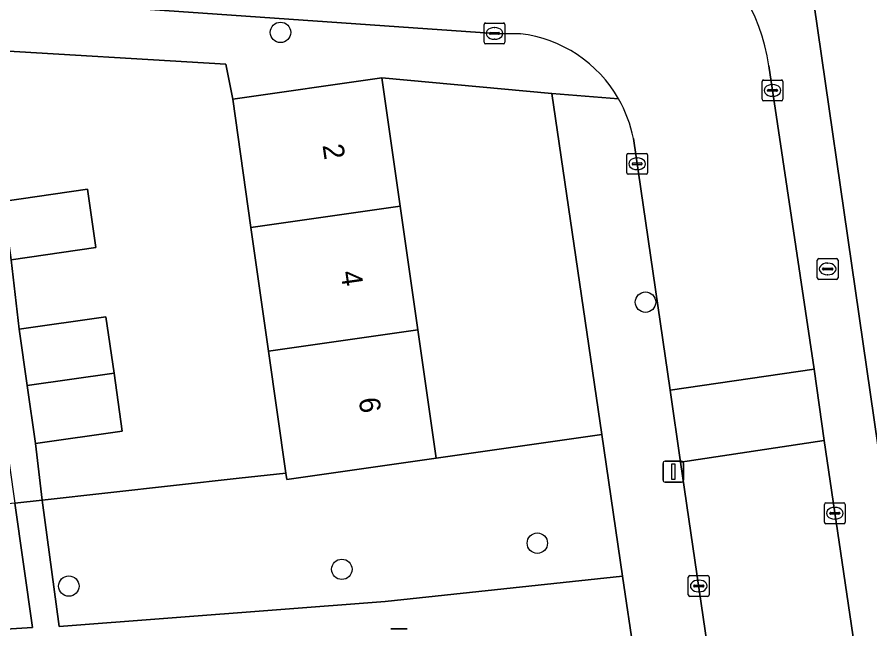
# Model space of a CAD drawing. Extents: x 159053 to 160042, y 380449 to 381423.
# Drawn here: x 159405.88 to 159446.78, y 381090.97 to 381120.32 of the extents above; entities that cross this region are included whole.
import ezdxf

# ---------------------------------------------------------------- set-up
doc = ezdxf.new("R2010")
doc.units = 0
for name, color, linetype in [('IMGEO_Boom', 7, 'Continuous'), ('IMGEO_Brandkraan', 7, 'Continuous'), ('IMGEO_Erf', 7, 'Continuous'), ('IMGEO_Groenvoorziening', 7, 'Continuous'), ('IMGEO_Kolk', 7, 'Continuous'), ('IMGEO_Lichtmast', 7, 'Continuous'), ('IMGEO_Muur', 7, 'Continuous'), ('IMGEO_Pand', 7, 'Continuous'), ('IMGEO_Pand_nummerreeks', 7, 'Continuous'), ('IMGEO_Rijbaan_lokaal_open', 7, 'Continuous'), ('IMGEO_Voetpad_open', 7, 'Continuous')]:
    doc.layers.add(name, color=color, linetype=linetype)

msp = doc.modelspace()

# ---------------------------------------------------------------- linework, layer by layer
at = {"layer": 'IMGEO_Boom'}
for centre in [(159418.511, 381119.583), (159436.016, 381106.642), (159430.829, 381095.081), (159421.453, 381093.827), (159408.362, 381093.023)]:
    msp.add_circle(centre, 0.489, dxfattribs=at)
at = {"layer": 'IMGEO_Brandkraan'}
for p, q in [((159444.251, 381107.808), (159444.251, 381108.66)), ((159444.326, 381108.734), (159445.178, 381108.734)), ((159444.739, 381108.514), (159444.764, 381108.514)), ((159445.252, 381108.66), (159445.252, 381107.808)), ((159444.51, 381108.228), (159444.51, 381108.24)), ((159444.948, 381108.191), (159444.55, 381108.191)), ((159444.553, 381108.277), (159444.951, 381108.277)), ((159444.994, 381108.24), (159444.994, 381108.228)), ((159445.178, 381107.734), (159444.326, 381107.734)), ((159444.762, 381107.954), (159444.737, 381107.954))]:
    msp.add_line(p, q, dxfattribs=at)
for points in [[(159444.251, 381107.808), (159444.251, 381108.66)], [(159444.326, 381108.734), (159445.178, 381108.734)], [(159445.252, 381108.66), (159445.252, 381107.808)], [(159445.178, 381107.734), (159444.326, 381107.734)]]:
    msp.add_lwpolyline(points, dxfattribs=at)
for centre, radius, start, end in [((159444.328, 381108.658), 0.0765, 91.552, 178.448), ((159444.328, 381108.658), 0.0765, 91.552, 178.448), ((159445.176, 381108.658), 0.0765, 1.552, 88.448), ((159445.176, 381108.658), 0.0765, 1.552, 88.448), ((159444.55, 381108.237), 0.0403, 85.8775, 175.7526), ((159444.547, 381108.227), 0.0366, 178.938, 274.7102), ((159444.951, 381108.234), 0.043, 264.8664, 352.4533), ((159444.955, 381108.239), 0.0386, 1.7309, 96.639), ((159444.328, 381107.81), 0.0765, 181.552, 268.448), ((159444.328, 381107.81), 0.0765, 181.552, 268.448), ((159445.176, 381107.81), 0.0765, 271.552, 358.448), ((159445.176, 381107.81), 0.0765, 271.552, 358.448)]:
    msp.add_arc(centre, radius, start, end, dxfattribs=at)
for centre, major_axis, ratio, start_param, end_param in [((159444.738, 381108.234), (-0.387, 0.002), 0.722429, 4.712389, 7.853982), ((159444.763, 381108.234), (-0.39, 0.002), 0.717154, 1.570796, 4.712389)]:
    msp.add_ellipse(centre, major_axis=major_axis, ratio=ratio, start_param=start_param, end_param=end_param, dxfattribs=at)
at = {"layer": 'IMGEO_Erf'}
for points in [[(159449.883, 381122.105), (159449.008, 381128.041), (159448.132, 381133.977), (159447.219, 381140.164), (159441.426, 381139.219), (159442.648, 381130.967), (159447.531, 381097.239), (159453.424, 381098.108), (159452.511, 381104.298), (159451.635, 381110.234), (159450.759, 381116.17)], [(159417.097, 381110.227), (159416.221, 381116.379), (159415.898, 381118.062), (159404.13, 381118.764), (159405.19, 381111.473), (159409.248, 381112.063), (159409.655, 381109.263), (159405.597, 381108.673), (159405.984, 381105.345), (159410.138, 381105.937), (159410.531, 381103.232), (159410.92, 381100.447), (159406.766, 381099.855), (159407.074, 381097.138), (159416.536, 381098.195), (159418.775, 381098.445), (159417.943, 381104.288)], [(159423.379, 381117.398), (159424.255, 381111.248), (159425.101, 381105.308), (159425.977, 381099.157), (159433.919, 381100.289), (159431.519, 381116.656)]]:
    msp.add_lwpolyline(points, close=True, dxfattribs=at)
at = {"layer": 'IMGEO_Groenvoorziening'}
for points in [[(159433.919, 381100.289), (159425.977, 381099.157), (159418.819, 381098.137), (159418.775, 381098.445), (159416.536, 381098.195), (159407.074, 381097.138), (159407.89, 381091.079), (159423.532, 381092.279), (159434.916, 381093.497)], [(159406.616, 381091.043), (159405.771, 381097), (159396.648, 381096.092), (159394.383, 381095.866), (159394.426, 381095.563), (159387.097, 381094.519), (159385.147, 381094.242), (159385.967, 381088.539), (159394.783, 381089.998), (159401.768, 381090.741)]]:
    msp.add_lwpolyline(points, close=True, dxfattribs=at)
at = {"layer": 'IMGEO_Kolk'}
for p, q in [((159428.276, 381119.106), (159428.276, 381119.958)), ((159428.351, 381120.032), (159429.203, 381120.032)), ((159429.277, 381119.958), (159429.277, 381119.106)), ((159428.535, 381119.526), (159428.535, 381119.538)), ((159428.973, 381119.489), (159428.575, 381119.489)), ((159428.578, 381119.575), (159428.976, 381119.575)), ((159428.764, 381119.812), (159428.789, 381119.812)), ((159429.019, 381119.538), (159429.019, 381119.526)), ((159429.203, 381119.032), (159428.351, 381119.032)), ((159428.787, 381119.252), (159428.762, 381119.252)), ((159441.607, 381116.372), (159441.607, 381117.224)), ((159441.682, 381117.298), (159442.534, 381117.298)), ((159442.095, 381117.078), (159442.12, 381117.078)), ((159442.608, 381117.224), (159442.608, 381116.372)), ((159441.866, 381116.792), (159441.866, 381116.804)), ((159442.304, 381116.755), (159441.906, 381116.755)), ((159441.909, 381116.841), (159442.307, 381116.841)), ((159442.35, 381116.804), (159442.35, 381116.792)), ((159442.534, 381116.298), (159441.682, 381116.298)), ((159442.118, 381116.518), (159442.093, 381116.518)), ((159435.115, 381112.852), (159435.115, 381113.704)), ((159435.19, 381113.778), (159436.042, 381113.778)), ((159436.116, 381113.704), (159436.116, 381112.852)), ((159435.417, 381113.321), (159435.815, 381113.321)), ((159435.603, 381113.558), (159435.628, 381113.558)), ((159435.374, 381113.272), (159435.374, 381113.284)), ((159435.812, 381113.235), (159435.414, 381113.235)), ((159435.626, 381112.998), (159435.601, 381112.998)), ((159435.858, 381113.284), (159435.858, 381113.272)), ((159436.042, 381112.778), (159435.19, 381112.778)), ((159444.596, 381096.091), (159444.596, 381096.943)), ((159444.671, 381097.017), (159445.523, 381097.017)), ((159445.597, 381096.943), (159445.597, 381096.091)), ((159444.898, 381096.56), (159445.296, 381096.56)), ((159445.084, 381096.797), (159445.109, 381096.797)), ((159444.855, 381096.511), (159444.855, 381096.523)), ((159445.293, 381096.474), (159444.895, 381096.474)), ((159445.107, 381096.237), (159445.082, 381096.237)), ((159445.339, 381096.523), (159445.339, 381096.511)), ((159445.523, 381096.017), (159444.671, 381096.017)), ((159438.069, 381092.601), (159438.069, 381093.453)), ((159438.144, 381093.527), (159438.996, 381093.527)), ((159438.557, 381093.307), (159438.582, 381093.307)), ((159439.07, 381093.453), (159439.07, 381092.601)), ((159438.328, 381093.021), (159438.328, 381093.033)), ((159438.766, 381092.984), (159438.368, 381092.984)), ((159438.371, 381093.07), (159438.769, 381093.07)), ((159438.812, 381093.033), (159438.812, 381093.021)), ((159438.996, 381092.527), (159438.144, 381092.527)), ((159438.58, 381092.747), (159438.555, 381092.747))]:
    msp.add_line(p, q, dxfattribs=at)
for points in [[(159428.276, 381119.106), (159428.276, 381119.958)], [(159428.351, 381120.032), (159429.203, 381120.032)], [(159429.277, 381119.958), (159429.277, 381119.106)], [(159429.203, 381119.032), (159428.351, 381119.032)], [(159441.607, 381116.372), (159441.607, 381117.224)], [(159441.682, 381117.298), (159442.534, 381117.298)], [(159442.608, 381117.224), (159442.608, 381116.372)], [(159442.534, 381116.298), (159441.682, 381116.298)], [(159435.115, 381112.852), (159435.115, 381113.704)], [(159435.19, 381113.778), (159436.042, 381113.778)], [(159436.116, 381113.704), (159436.116, 381112.852)], [(159436.042, 381112.778), (159435.19, 381112.778)], [(159444.596, 381096.091), (159444.596, 381096.943)], [(159444.671, 381097.017), (159445.523, 381097.017)], [(159445.597, 381096.943), (159445.597, 381096.091)], [(159445.523, 381096.017), (159444.671, 381096.017)], [(159438.069, 381092.601), (159438.069, 381093.453)], [(159438.144, 381093.527), (159438.996, 381093.527)], [(159439.07, 381093.453), (159439.07, 381092.601)], [(159438.996, 381092.527), (159438.144, 381092.527)]]:
    msp.add_lwpolyline(points, dxfattribs=at)
for centre, radius, start, end in [((159428.353, 381119.956), 0.0765, 91.552, 178.448), ((159428.353, 381119.956), 0.0765, 91.552, 178.448), ((159429.201, 381119.956), 0.0765, 1.552, 88.448), ((159429.201, 381119.956), 0.0765, 1.552, 88.448), ((159428.575, 381119.535), 0.0403, 85.8775, 175.7526), ((159428.572, 381119.525), 0.0366, 178.938, 274.7102), ((159428.976, 381119.532), 0.043, 264.8664, 352.4533), ((159428.98, 381119.537), 0.0386, 1.7309, 96.639), ((159428.353, 381119.108), 0.0765, 181.552, 268.448), ((159428.353, 381119.108), 0.0765, 181.552, 268.448), ((159429.201, 381119.108), 0.0765, 271.552, 358.448), ((159429.201, 381119.108), 0.0765, 271.552, 358.448), ((159441.684, 381117.222), 0.0765, 91.552, 178.448), ((159441.684, 381117.222), 0.0765, 91.552, 178.448), ((159442.532, 381117.222), 0.0765, 1.552, 88.448), ((159442.532, 381117.222), 0.0765, 1.552, 88.448), ((159441.906, 381116.801), 0.0403, 85.8775, 175.7526), ((159441.903, 381116.791), 0.0366, 178.938, 274.7102), ((159442.307, 381116.798), 0.043, 264.8664, 352.4533), ((159442.311, 381116.803), 0.0386, 1.7309, 96.639), ((159441.684, 381116.374), 0.0765, 181.552, 268.448), ((159441.684, 381116.374), 0.0765, 181.552, 268.448), ((159442.532, 381116.374), 0.0765, 271.552, 358.448), ((159442.532, 381116.374), 0.0765, 271.552, 358.448), ((159435.192, 381113.702), 0.0765, 91.552, 178.448), ((159435.192, 381113.702), 0.0765, 91.552, 178.448), ((159436.04, 381113.702), 0.0765, 1.552, 88.448), ((159436.04, 381113.702), 0.0765, 1.552, 88.448), ((159435.414, 381113.281), 0.0403, 85.8775, 175.7526), ((159435.819, 381113.283), 0.0386, 1.7309, 96.639), ((159435.411, 381113.271), 0.0366, 178.938, 274.7102), ((159435.815, 381113.278), 0.043, 264.8664, 352.4533), ((159435.192, 381112.854), 0.0765, 181.552, 268.448), ((159435.192, 381112.854), 0.0765, 181.552, 268.448), ((159436.04, 381112.854), 0.0765, 271.552, 358.448), ((159436.04, 381112.854), 0.0765, 271.552, 358.448), ((159444.673, 381096.941), 0.0765, 91.552, 178.448), ((159444.673, 381096.941), 0.0765, 91.552, 178.448), ((159445.521, 381096.941), 0.0765, 1.552, 88.448), ((159445.521, 381096.941), 0.0765, 1.552, 88.448), ((159444.895, 381096.52), 0.0403, 85.8775, 175.7526), ((159445.3, 381096.522), 0.0386, 1.7309, 96.639), ((159444.892, 381096.51), 0.0366, 178.938, 274.7102), ((159445.296, 381096.517), 0.043, 264.8664, 352.4533), ((159444.673, 381096.093), 0.0765, 181.552, 268.448), ((159444.673, 381096.093), 0.0765, 181.552, 268.448), ((159445.521, 381096.093), 0.0765, 271.552, 358.448), ((159445.521, 381096.093), 0.0765, 271.552, 358.448), ((159438.146, 381093.451), 0.0765, 91.552, 178.448), ((159438.146, 381093.451), 0.0765, 91.552, 178.448), ((159438.994, 381093.451), 0.0765, 1.552, 88.448), ((159438.994, 381093.451), 0.0765, 1.552, 88.448), ((159438.368, 381093.03), 0.0403, 85.8775, 175.7526), ((159438.365, 381093.02), 0.0366, 178.938, 274.7102), ((159438.769, 381093.027), 0.043, 264.8664, 352.4533), ((159438.773, 381093.032), 0.0386, 1.7309, 96.639), ((159438.146, 381092.603), 0.0765, 181.552, 268.448), ((159438.146, 381092.603), 0.0765, 181.552, 268.448), ((159438.994, 381092.603), 0.0765, 271.552, 358.448), ((159438.994, 381092.603), 0.0765, 271.552, 358.448)]:
    msp.add_arc(centre, radius, start, end, dxfattribs=at)
for centre, major_axis, ratio, start_param, end_param in [((159428.763, 381119.532), (-0.387, 0.002), 0.722429, 4.712389, 7.853982), ((159428.788, 381119.532), (-0.39, 0.002), 0.717154, 1.570796, 4.712389), ((159442.094, 381116.798), (-0.387, 0.002), 0.722429, 4.712389, 7.853982), ((159442.119, 381116.798), (-0.39, 0.002), 0.717154, 1.570796, 4.712389), ((159435.602, 381113.278), (-0.387, 0.002), 0.722429, 4.712389, 7.853982), ((159435.627, 381113.278), (-0.39, 0.002), 0.717154, 1.570796, 4.712389), ((159445.083, 381096.517), (-0.387, 0.002), 0.722429, 4.712389, 7.853982), ((159445.108, 381096.517), (-0.39, 0.002), 0.717154, 1.570796, 4.712389), ((159438.556, 381093.027), (-0.387, 0.002), 0.722429, 4.712389, 7.853982), ((159438.581, 381093.027), (-0.39, 0.002), 0.717154, 1.570796, 4.712389)]:
    msp.add_ellipse(centre, major_axis=major_axis, ratio=ratio, start_param=start_param, end_param=end_param, dxfattribs=at)
at = {"layer": 'IMGEO_Lichtmast'}
for p, q in [((159436.956, 381099.01), (159437.746, 381099.01)), ((159437.746, 381099.01), (159436.956, 381099.01)), ((159436.856, 381098.11), (159436.856, 381098.91)), ((159436.856, 381098.91), (159436.856, 381098.11)), ((159437.846, 381098.91), (159437.846, 381098.11)), ((159437.846, 381098.11), (159437.846, 381098.91)), ((159437.746, 381098.01), (159436.956, 381098.01)), ((159436.956, 381098.01), (159437.746, 381098.01)), ((159423.797, 381090.968), (159424.587, 381090.968)), ((159424.587, 381090.968), (159423.797, 381090.968))]:
    msp.add_line(p, q, dxfattribs=at)
msp.add_lwpolyline([(159437.276, 381098.885), (159437.426, 381098.885), (159437.426, 381098.135), (159437.276, 381098.135), (159437.276, 381098.885)], dxfattribs=at)
for centre, start, end in [((159436.956, 381098.91), 90, 180), ((159436.956, 381098.91), 90, 180), ((159437.746, 381098.91), 0, 90), ((159437.746, 381098.91), 360, 90), ((159436.956, 381098.11), 180, 270), ((159436.956, 381098.11), 180, 270), ((159437.746, 381098.11), 270, 0), ((159437.746, 381098.11), 270, 0)]:
    msp.add_arc(centre, 0.1, start, end, dxfattribs=at)
at = {"layer": 'IMGEO_Muur'}
msp.add_lwpolyline([(159404.13, 381118.764), (159415.898, 381118.062), (159416.221, 381116.379)], dxfattribs=at)
at = {"layer": 'IMGEO_Pand'}
for points in [[(159424.255, 381111.248), (159423.379, 381117.398), (159416.221, 381116.379), (159417.097, 381110.227)], [(159405.597, 381108.673), (159409.655, 381109.263), (159409.248, 381112.063), (159405.19, 381111.473)], [(159417.943, 381104.288), (159425.101, 381105.308), (159424.255, 381111.248), (159417.097, 381110.227)], [(159405.984, 381105.345), (159406.369, 381102.639), (159410.531, 381103.232), (159410.138, 381105.937)], [(159417.943, 381104.288), (159418.775, 381098.445), (159418.819, 381098.137), (159425.977, 381099.157), (159425.101, 381105.308)], [(159410.531, 381103.232), (159406.369, 381102.639), (159406.766, 381099.855), (159410.92, 381100.447)]]:
    msp.add_lwpolyline(points, close=True, dxfattribs=at)
at = {"layer": 'IMGEO_Rijbaan_lokaal_open'}
for points in [[(159432.282, 381126.275), (159429.161, 381126.499), (159424.078, 381126.859), (159412.055, 381127.71), (159411.579, 381120.723), (159428.777, 381119.532), (159430.026, 381119.52)], [(159435.439, 381114.494), (159437.198, 381102.422), (159444.103, 381103.428), (159441.932, 381117.978)]]:
    msp.add_lwpolyline(points, dxfattribs=at)
for points in [[(159444.583, 381100.003), (159444.103, 381103.428), (159437.198, 381102.422), (159437.701, 381098.967)], [(159450.287, 381061.32), (159444.583, 381100.003), (159437.701, 381098.967), (159443.344, 381060.378)]]:
    msp.add_lwpolyline(points, close=True, dxfattribs=at)
for centre, radius, start, end in [((159432.499, 381116.558), 9.539, 8.5595, 55.1421), ((159429.251, 381113.257), 6.311, 29.8507, 82.9495), ((159429.239, 381113.255), 6.323, 11.3028, 29.8093)]:
    msp.add_arc(centre, radius, start, end, dxfattribs=at)
at = {"layer": 'IMGEO_Voetpad_open'}
for points in [[(159448.814, 381088.274), (159448.096, 381093.308), (159447.686, 381096.187), (159447.619, 381096.645), (159447.531, 381097.239), (159442.648, 381130.967), (159441.426, 381139.219), (159441.281, 381139.203), (159441.061, 381140.618), (159440.41, 381144.797), (159439.474, 381144.862), (159437.288, 381145.013), (159433.918, 381145.257), (159429.225, 381145.596), (159426.937, 381145.736), (159425.903, 381145.825), (159425.535, 381140.626), (159425.073, 381140.663), (159424.569, 381133.226), (159424.259, 381129.362), (159424.078, 381126.859), (159429.161, 381126.499), (159432.282, 381126.275)], [(159430.026, 381119.52), (159428.777, 381119.532), (159411.579, 381120.723), (159408.288, 381120.979), (159390.325, 381122.15), (159382.229, 381121.007)], [(159383.66, 381118.652), (159390.989, 381119.696), (159402.491, 381118.862), (159404.13, 381118.764), (159415.898, 381118.062), (159416.221, 381116.379), (159423.379, 381117.398), (159431.519, 381116.656), (159434.725, 381116.398)], [(159441.932, 381117.978), (159444.103, 381103.428), (159444.583, 381100.003), (159450.287, 381061.32), (159450.806, 381057.803), (159453.929, 381036.365), (159454.981, 381029.422), (159458.014, 381008.022), (159458.502, 381004.55), (159459.721, 380996.557), (159460.213, 380993.326), (159465.54, 380994.899)], [(159434.725, 381116.398), (159431.519, 381116.656), (159433.919, 381100.289), (159434.916, 381093.497), (159435.479, 381089.722), (159448.874, 381000), (159449.622, 380994.989)], [(159447.686, 381030.883), (159446.657, 381037.89), (159443.858, 381056.823), (159443.344, 381060.378), (159437.701, 381098.967), (159437.198, 381102.422), (159435.439, 381114.494)], [(159435.479, 381089.722), (159434.916, 381093.497), (159423.532, 381092.279), (159407.89, 381091.079), (159407.074, 381097.138), (159405.771, 381097), (159406.616, 381091.043), (159401.768, 381090.741), (159394.783, 381089.998), (159385.967, 381088.539), (159386.502, 381084.962)]]:
    msp.add_lwpolyline(points, dxfattribs=at)
msp.add_lwpolyline([(159405.597, 381108.673), (159405.19, 381111.473), (159404.13, 381118.764), (159402.491, 381118.862), (159402.633, 381117.927), (159403.052, 381115.16), (159403.425, 381112.363), (159404.432, 381106.058), (159404.851, 381103.295), (159405.257, 381100.62), (159405.771, 381097), (159407.074, 381097.138), (159406.766, 381099.855), (159406.369, 381102.639), (159405.984, 381105.345)], close=True, dxfattribs=at)
for centre, radius, start, end in [((159432.499, 381116.558), 9.539, 8.5595, 55.1421), ((159429.251, 381113.257), 6.311, 29.8507, 82.9495), ((159429.239, 381113.255), 6.323, 11.3028, 29.8093)]:
    msp.add_arc(centre, radius, start, end, dxfattribs=at)

# ---------------------------------------------------------------- texts
at = {"layer": 'IMGEO_Pand_nummerreeks'}
for s, p in [('2', (159420.525, 381114.17)), ('4', (159421.392, 381108.088)), ('6', (159422.258, 381102.007))]:
    msp.add_text(s, height=1, rotation=278.1059, dxfattribs=at).set_placement(p)

doc.saveas('drawing.dxf')
